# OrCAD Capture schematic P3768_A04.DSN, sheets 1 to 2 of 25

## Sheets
1 0024_FAN, DEBUG and EEPROM: size Custom
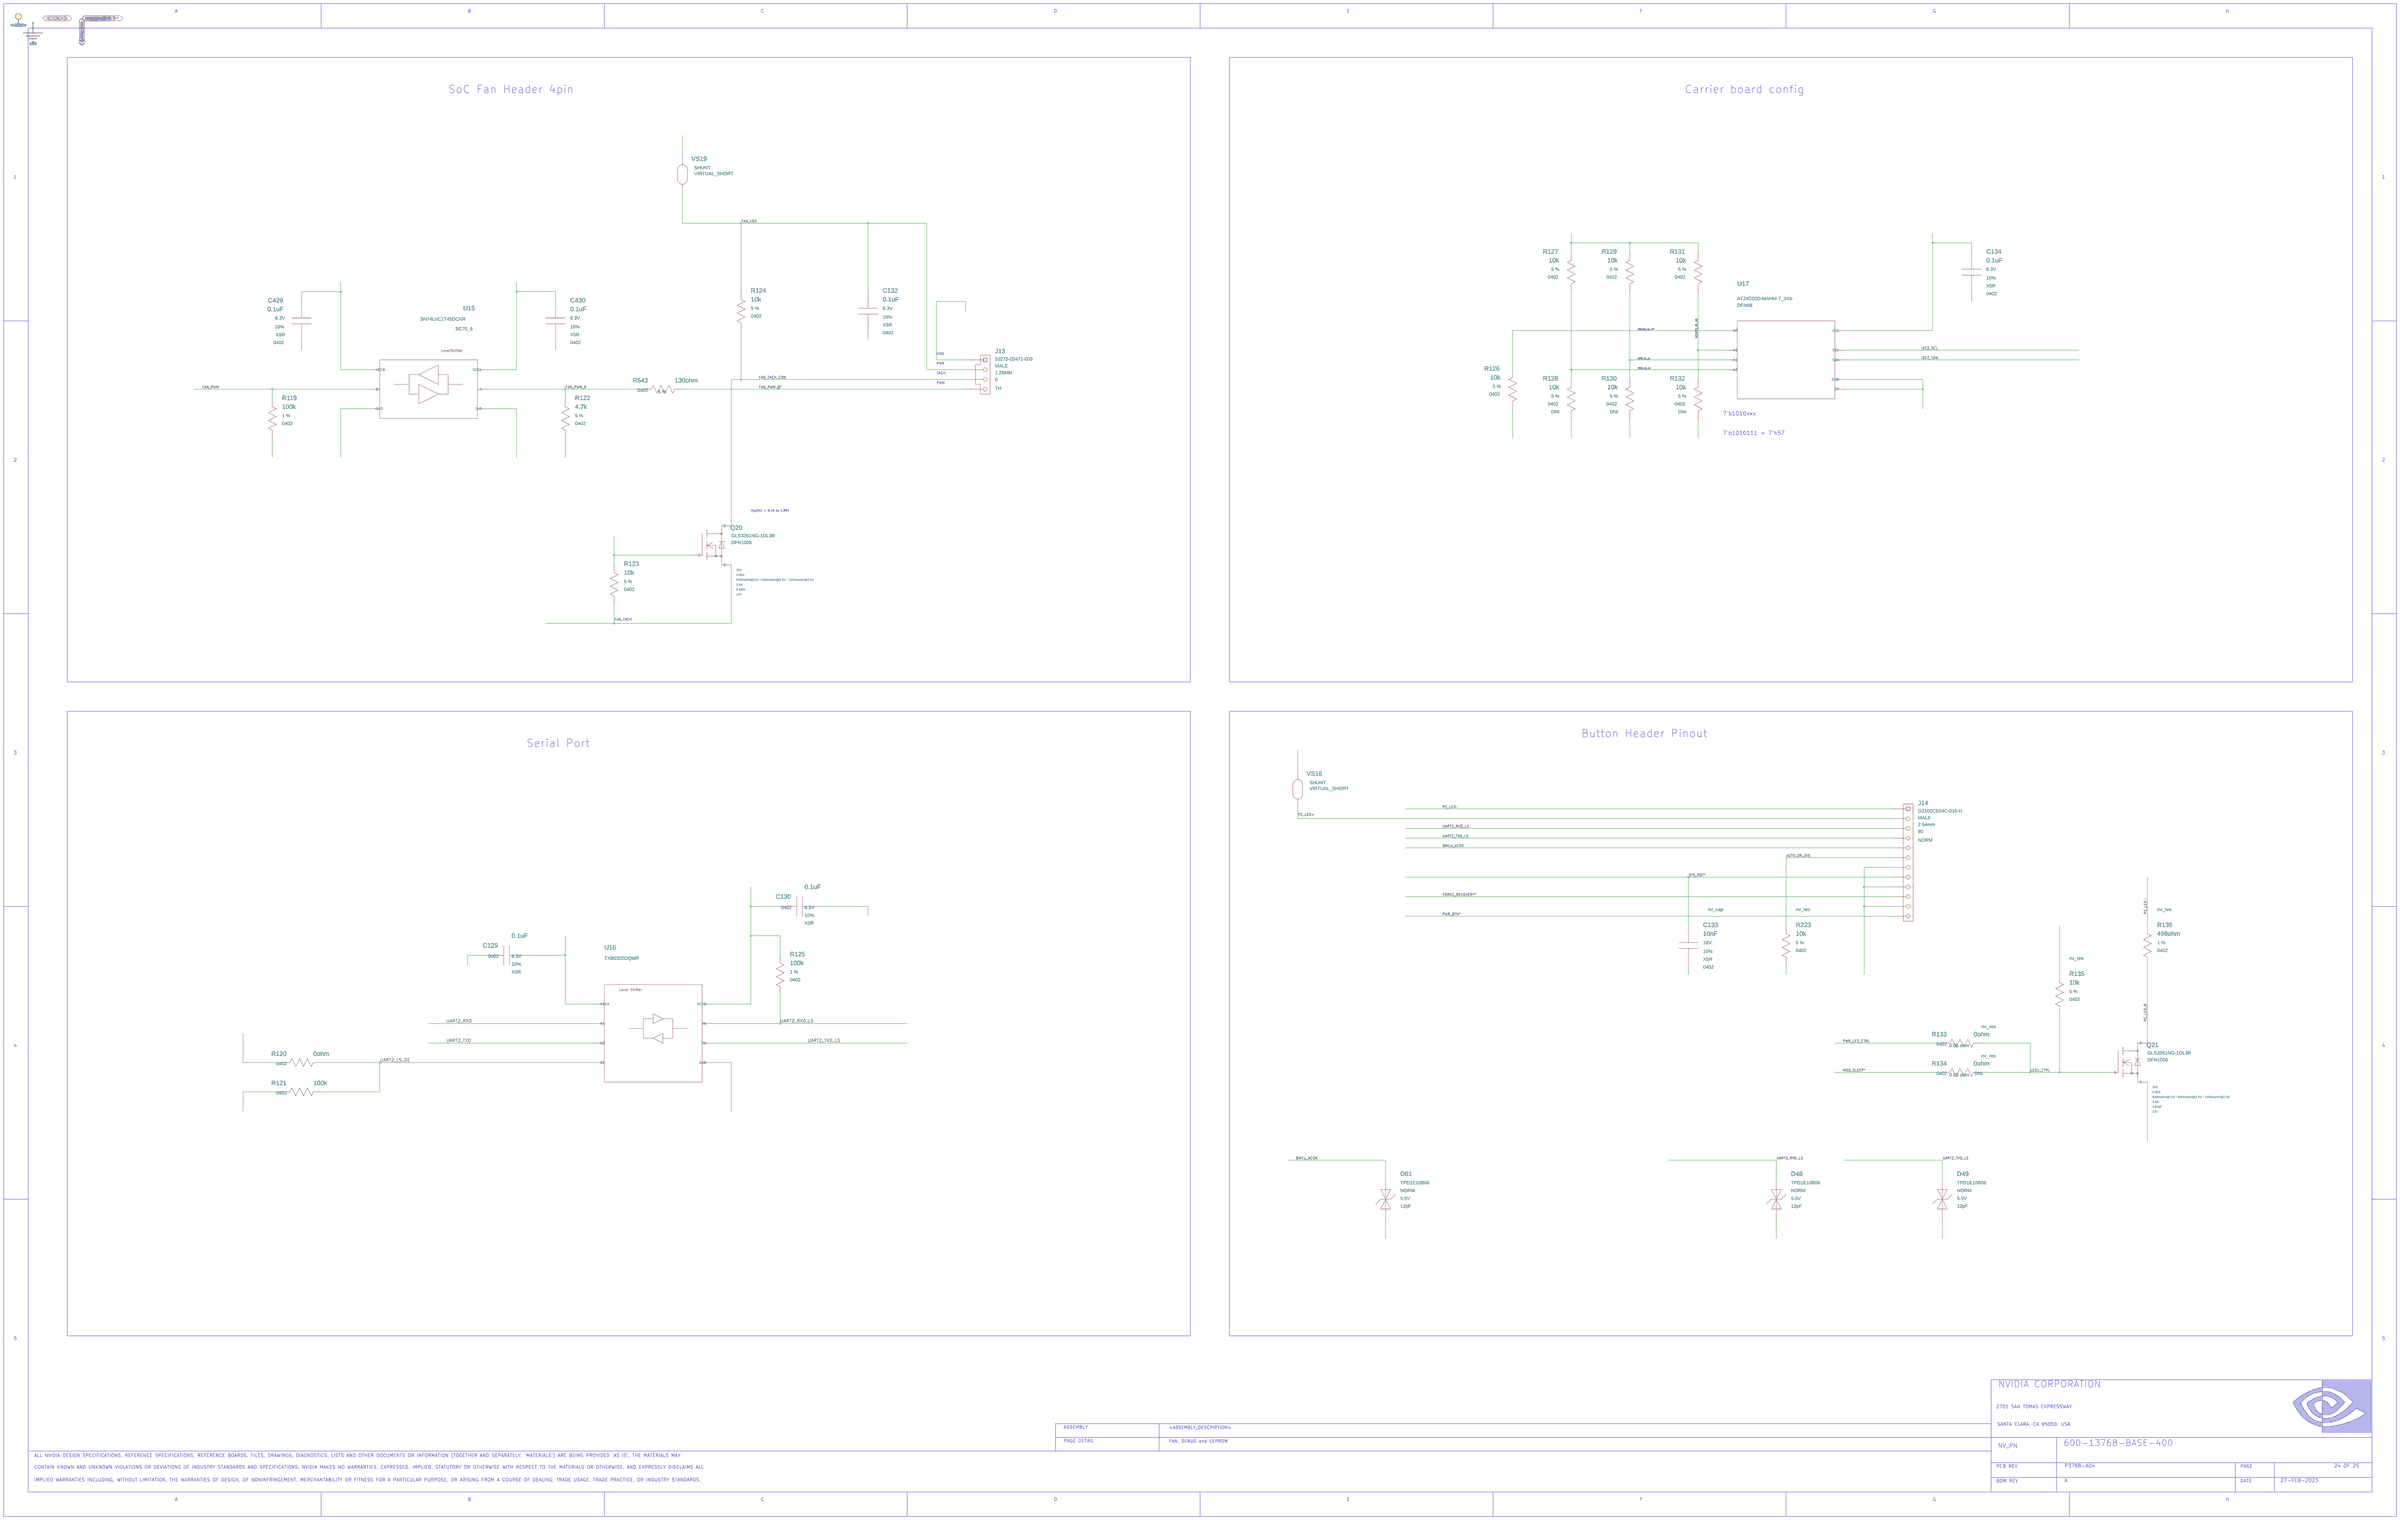
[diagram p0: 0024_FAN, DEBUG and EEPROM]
2 0023_40PIN GPIO Expansion HDR: size Custom
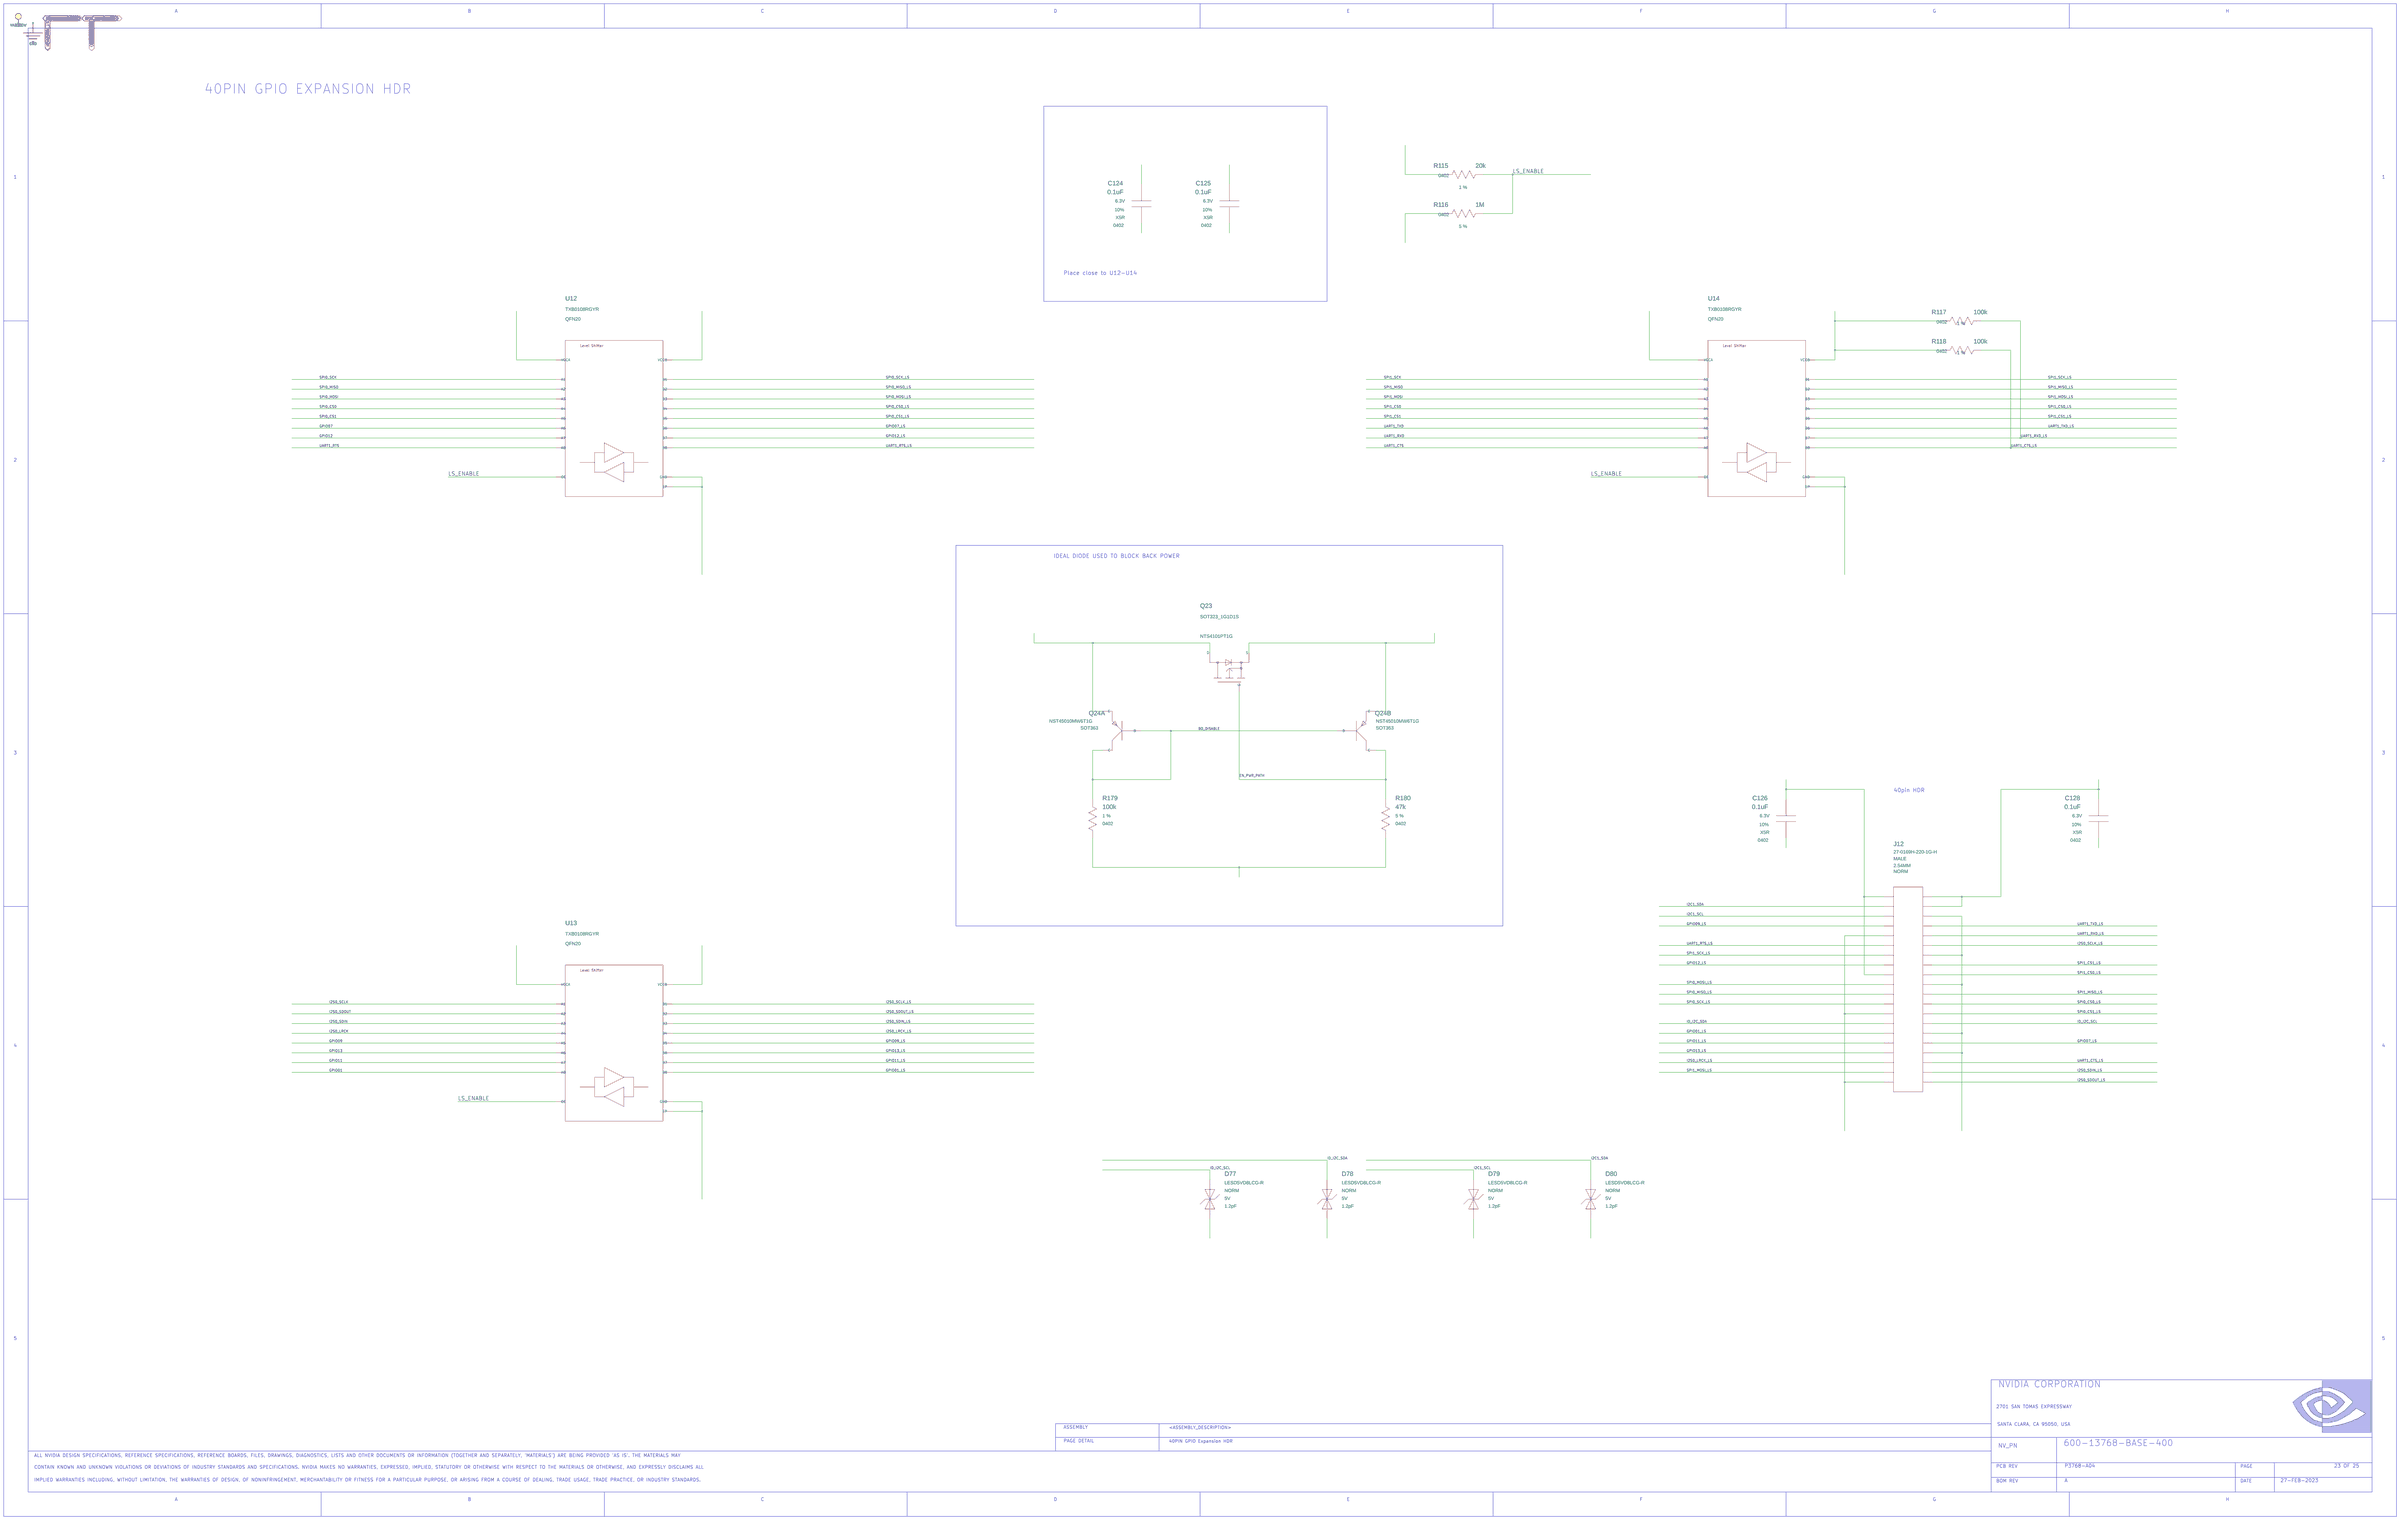
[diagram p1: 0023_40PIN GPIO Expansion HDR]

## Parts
sheet 0023_40PIN GPIO Expansion HDR
C124  0.1uF  [0402]
C125  0.1uF  [0402]
C126  0.1uF  [0402]
C128  0.1uF  [0402]
D77  D_ESD  [DIODE_SMD_010X006_B]
D78  D_ESD  [DIODE_SMD_010X006_B]
D79  D_ESD  [DIODE_SMD_010X006_B]
D80  D_ESD  [DIODE_SMD_010X006_B]
J12  HDR_2X20  [CON_HDR_002X020_TH_ST_M_P025_B]
Q23  Q_FET_P_ENH  [SOT323]
Q24  Q_PNP  [SC70_6]  (sections A,B)
R115  20k  [0402]
R116  1M  [0402]
R117  100k  [0402]
R118  100k  [0402]
R179  100k  [0402]
R180  47k  [0402]
U12  U_LEVSHFT_TXB0108  [QFN020R_P050_0045X0035_T031X021_VIAS]
U13  U_LEVSHFT_TXB0108  [QFN020R_P050_0045X0035_T031X021_VIAS]
U14  U_LEVSHFT_TXB0108  [QFN020R_P050_0045X0035_T031X021_VIAS]
sheet 0024_FAN, DEBUG and EEPROM
C129  0.1uF  [0402]
C130  0.1uF  [0402]
C132  0.1uF  [0402]
C133  10nF  [0402]
C134  0.1uF  [0402]
C429  0.1uF  [0402]
C430  0.1uF  [0402]
D48  D_ESD  [DIODE_SMD_010X060]
D49  D_ESD  [DIODE_SMD_010X060]
D81  D_ESD  [DIODE_SMD_010X060]
J13  CON_B2W_1X4  [CON_MISC_004_TH_ST_M_P013_WTB]
J14  HDR_1X12  [CON_HDR_001X012_TH_RA_M_P025]
Q20  Q_FET_N_ENH  [DFET_003_SMD_010X006_B]
Q21  Q_FET_N_ENH  [DFET_003_SMD_010X006_B]
R119  100k  [0402]
R120  0ohm  [0402]
R121  100k  [0402]
R122  4.7k  [0402]
R123  10k  [0402]
R124  10k  [0402]
R125  100k  [0402]
R126  10k  [0402]
R127  10k  [0402]
R128  10k  [0402]
R129  10k  [0402]
R130  10k  [0402]
R131  10k  [0402]
R132  10k  [0402]
R133  0ohm  [0402]
R134  0ohm  [0402]
R135  10k  [0402]
R136  499ohm  [0402]
R223  10k  [0402]
R543  130ohm  [0402]
U15  U_LEVSHFT_3STATE  [SC70_6]
U16  U_LEVSHFT_TXB0302  [DFN08_P040_018X012]
U17  U_MEM_EE_I2C  [DFN08_P050_020X030_T014X014]
VS16  VIRTUAL_SHORT  [VIRTUAL_SHORT]
VS19  VIRTUAL_SHORT  [VIRTUAL_SHORT]

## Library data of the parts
C124 = C#1: ASSEMBLY: GPIO_HDR; CDS_LIB: discrete; CDS_PART_NAME: C_0402-0.1UF,X5R,10%,6.3V,039-0007-000; CDS_PHYS_PART_NAME: C_0402-0.1UF,X5R,10%,6.3V,039-0007-000-0.1UF,039-0007-000; CDS_SEC: 1; CHIPS_PART_NAME: C; DEVICE_TYPENAME: C_0402-01UFX5R1063V039-0007-000-01UF039-0007-000; DRAWING: @P3768_A04_LIB.P3768_A04(SCH_1):PAGE23; ESL: N/A; ESR: N/A; MAT: X5R; MAX_VOLTAGE: 6.3V; NV_PN: 039-0007-000; PATH: I68; PHYS_PAGE: 23; PSPICETEMPLATE: X^@REFDES  %1    %2   @NV_PN; ROT: 2; SEC: 1; SIGNAL_MODEL: nv_cap; TOL: 10%; VER: 1; XY: (-6300,6600)
C125 = C#1: ASSEMBLY: GPIO_HDR; CDS_LIB: discrete; CDS_PART_NAME: C_0402-0.1UF,X5R,10%,6.3V,039-0007-000; CDS_PHYS_PART_NAME: C_0402-0.1UF,X5R,10%,6.3V,039-0007-000-0.1UF,039-0007-000; CDS_SEC: 1; CHIPS_PART_NAME: C; DEVICE_TYPENAME: C_0402-01UFX5R1063V039-0007-000-01UF039-0007-000; DRAWING: @P3768_A04_LIB.P3768_A04(SCH_1):PAGE23; ESL: N/A; ESR: N/A; MAT: X5R; MAX_VOLTAGE: 6.3V; NV_PN: 039-0007-000; PATH: I57; PHYS_PAGE: 23; PSPICETEMPLATE: X^@REFDES  %1    %2   @NV_PN; ROT: 2; SEC: 1; SIGNAL_MODEL: nv_cap; TOL: 10%; VER: 1; XY: (-5850,6600)
C126 = C#1: ASSEMBLY: GPIO_HDR; CDS_LIB: discrete; CDS_PART_NAME: C_0402-0.1UF,X5R,10%,6.3V,039-0007-000; CDS_PHYS_PART_NAME: C_0402-0.1UF,X5R,10%,6.3V,039-0007-000-0.1UF,039-0007-000; CDS_SEC: 1; CHIPS_PART_NAME: C; DEVICE_TYPENAME: C_0402-01UFX5R1063V039-0007-000-01UF039-0007-000; DRAWING: @P3768_A04_LIB.P3768_A04(SCH_1):PAGE23; ESL: N/A; ESR: N/A; MAT: X5R; MAX_VOLTAGE: 6.3V; NV_PN: 039-0007-000; PATH: I40; PHYS_PAGE: 23; PSPICETEMPLATE: X^@REFDES  %1    %2   @NV_PN; ROT: 2; SEC: 1; SIGNAL_MODEL: nv_cap; TOL: 10%; VER: 1; XY: (-3000,3450)
C128 = C#1: ASSEMBLY: GPIO_HDR; CDS_LIB: discrete; CDS_PART_NAME: C_0402-0.1UF,X5R,10%,6.3V,039-0007-000; CDS_PHYS_PART_NAME: C_0402-0.1UF,X5R,10%,6.3V,039-0007-000-0.1UF,039-0007-000; CDS_SEC: 1; CHIPS_PART_NAME: C; DEVICE_TYPENAME: C_0402-01UFX5R1063V039-0007-000-01UF039-0007-000; DRAWING: @P3768_A04_LIB.P3768_A04(SCH_1):PAGE23; ESL: N/A; ESR: N/A; MAT: X5R; MAX_VOLTAGE: 6.3V; NV_PN: 039-0007-000; PATH: I31; PHYS_PAGE: 23; PSPICETEMPLATE: X^@REFDES  %1    %2   @NV_PN; ROT: 2; SEC: 1; SIGNAL_MODEL: nv_cap; TOL: 10%; VER: 1; XY: (-1400,3450)
D77 = D_ESD: ASSEMBLY: GPIO_HDR; BREAKDOWN_VOLTAGE_MIN_TYP: 5.5V; CAPACITANCE_MAX_TYP: 1.2pF; CDS_LIB: discrete; CDS_PART_NAME: D_ESD_NORM-LESD5VD8LCG-R,1 LINE,BI-DIRECTIONAL,5V,0.05UA,5.5V,10V@2A,1.2PF,090-0172-000; CDS_PHYS_PART_NAME: D_ESD_NORM-LESD5VD8LCG-R,1 LINE,BI-DIRECTIONAL,5V,0.05UA,5.5V,10V@2A,1.2PF,090-0172-000-090-0172-000; CDS_SEC: 1; CLAMPING_VOLTAGE: 10V@2A; CONFIGURATION: 1 Line; DEVICE_TYPENAME: D_ESD_NORM-LESD5VD8LCG-R1LINEBI-DIRECTIONAL5V005UA55V10V2A12PF090-0172-000-090-0172-000; DRAWING: @P3768_A04_LIB.P3768_A04(SCH_1):PAGE23; MAX_REVERSE_LEAKAGE_CURRENT: 0.05uA; MAX_REVERSE_VOLTAGE: 5V; NV_NAME: LESD5VD8LCG-R; NV_PN: 090-0172-000; PACK_TYPE: NORM; PATH: I84; PHYS_PAGE: 23; POLARITY: Bi-Directional; ROT: 0; SEC: 1; VER: 2; XY: (-5950,1500)
D78 = D_ESD: ASSEMBLY: GPIO_HDR; BREAKDOWN_VOLTAGE_MIN_TYP: 5.5V; CAPACITANCE_MAX_TYP: 1.2pF; CDS_LIB: discrete; CDS_PART_NAME: D_ESD_NORM-LESD5VD8LCG-R,1 LINE,BI-DIRECTIONAL,5V,0.05UA,5.5V,10V@2A,1.2PF,090-0172-000; CDS_PHYS_PART_NAME: D_ESD_NORM-LESD5VD8LCG-R,1 LINE,BI-DIRECTIONAL,5V,0.05UA,5.5V,10V@2A,1.2PF,090-0172-000-090-0172-000; CDS_SEC: 1; CLAMPING_VOLTAGE: 10V@2A; CONFIGURATION: 1 Line; DEVICE_TYPENAME: D_ESD_NORM-LESD5VD8LCG-R1LINEBI-DIRECTIONAL5V005UA55V10V2A12PF090-0172-000-090-0172-000; DRAWING: @P3768_A04_LIB.P3768_A04(SCH_1):PAGE23; MAX_REVERSE_LEAKAGE_CURRENT: 0.05uA; MAX_REVERSE_VOLTAGE: 5V; NV_NAME: LESD5VD8LCG-R; NV_PN: 090-0172-000; PACK_TYPE: NORM; PATH: I82; PHYS_PAGE: 23; POLARITY: Bi-Directional; ROT: 0; SEC: 1; VER: 2; XY: (-5350,1500)
D79 = D_ESD: ASSEMBLY: GPIO_HDR; BREAKDOWN_VOLTAGE_MIN_TYP: 5.5V; CAPACITANCE_MAX_TYP: 1.2pF; CDS_LIB: discrete; CDS_PART_NAME: D_ESD_NORM-LESD5VD8LCG-R,1 LINE,BI-DIRECTIONAL,5V,0.05UA,5.5V,10V@2A,1.2PF,090-0172-000; CDS_PHYS_PART_NAME: D_ESD_NORM-LESD5VD8LCG-R,1 LINE,BI-DIRECTIONAL,5V,0.05UA,5.5V,10V@2A,1.2PF,090-0172-000-090-0172-000; CDS_SEC: 1; CLAMPING_VOLTAGE: 10V@2A; CONFIGURATION: 1 Line; DEVICE_TYPENAME: D_ESD_NORM-LESD5VD8LCG-R1LINEBI-DIRECTIONAL5V005UA55V10V2A12PF090-0172-000-090-0172-000; DRAWING: @P3768_A04_LIB.P3768_A04(SCH_1):PAGE23; MAX_REVERSE_LEAKAGE_CURRENT: 0.05uA; MAX_REVERSE_VOLTAGE: 5V; NV_NAME: LESD5VD8LCG-R; NV_PN: 090-0172-000; PACK_TYPE: NORM; PATH: I79; PHYS_PAGE: 23; POLARITY: Bi-Directional; ROT: 0; SEC: 1; VER: 2; XY: (-4600,1500)
D80 = D_ESD: ASSEMBLY: GPIO_HDR; BREAKDOWN_VOLTAGE_MIN_TYP: 5.5V; CAPACITANCE_MAX_TYP: 1.2pF; CDS_LIB: discrete; CDS_PART_NAME: D_ESD_NORM-LESD5VD8LCG-R,1 LINE,BI-DIRECTIONAL,5V,0.05UA,5.5V,10V@2A,1.2PF,090-0172-000; CDS_PHYS_PART_NAME: D_ESD_NORM-LESD5VD8LCG-R,1 LINE,BI-DIRECTIONAL,5V,0.05UA,5.5V,10V@2A,1.2PF,090-0172-000-090-0172-000; CDS_SEC: 1; CLAMPING_VOLTAGE: 10V@2A; CONFIGURATION: 1 Line; DEVICE_TYPENAME: D_ESD_NORM-LESD5VD8LCG-R1LINEBI-DIRECTIONAL5V005UA55V10V2A12PF090-0172-000-090-0172-000; DRAWING: @P3768_A04_LIB.P3768_A04(SCH_1):PAGE23; MAX_REVERSE_LEAKAGE_CURRENT: 0.05uA; MAX_REVERSE_VOLTAGE: 5V; NV_NAME: LESD5VD8LCG-R; NV_PN: 090-0172-000; PACK_TYPE: NORM; PATH: I78; PHYS_PAGE: 23; POLARITY: Bi-Directional; ROT: 0; SEC: 1; VER: 2; XY: (-4000,1500)
J12 = HDR_2X20: ANGLE: 0; ASSEMBLY: GPIO_HDR; CDS_LIB: electro_mechanic; CDS_PART_NAME: HDR_2X20_NORM-27-0169H-220-1G-H,MALE,2.54MM,0,YES,NO,NO,1000 V,3 A,074-0221-000; CDS_PHYS_PART_NAME: HDR_2X20_NORM-27-0169H-220-1G-H,MALE,2.54MM,0,YES,NO,NO,1000 V,3 A,074-0221-000-074-0221-000; CDS_SEC: 1; DEVICE_TYPENAME: HDR_2X20_NORM-27-0169H-220-1G-HMALE254MM0YESNONO1000V3A074-0221-000-074-0221-000; DRAWING: @P3768_A04_LIB.P3768_A04(SCH_1):PAGE23; GENDER: MALE; LATCHING: NO; MAX_CURRENT: 3 A; MAX_VOLTAGE: 1000 V; NV_NAME: 27-0169H-220-1G-H; NV_PN: 074-0221-000; PACK_TYPE: NORM; PATH: I1; PHYS_PAGE: 23; PITCH: 2.54MM; REFLOW: YES; ROT: 0; SEC: 1; SHROUDED: NO; VER: 1; XY: (-2350,2550)
Q23 = Q_FET_P_ENH#2: ASSEMBLY: GPIO_HDR; CDS_LIB: discrete; CDS_PART_NAME: Q_FET_P_ENH_SOT323_1G1D1S-NTS4101PT1G,-20V,0MOHM@10V / 120MOHM@4.5V / 160MOHM@2.5V,-1.37A,-4A,8V,0.329W,[ ]@10V / 9NC@4.5V / [ ]@2.5V,300-0859-000; CDS_PHYS_PART_NAME: Q_FET_P_ENH_SOT323_1G1D1S-NTS4101PT1G,-20V,0MOHM@10V / 120MOHM@4.5V / 160MOHM@2.5V,-1.37A,-4A,8V,0.329W,[ ]@10V / 9NC@4.5V / [B; CDS_SEC: 1; CONTINUOUS_CURRENT: -1.37A; DEVICE_TYPENAME: Q_FET_P_ENH_SOT323_1G1D1S-NTS4101PT1G-20V0MOHM10V120MOHM45V160MOHM25V-137A-4A8V0329W10V9NC45VB; DRAWING: @P3768_A04_LIB.P3768_A04(SCH_1):PAGE23; MAX_CURRENT: -4A; MAX_VOLTAGE: -20V; MAX_WATTAGE: 0.329W; NV_NAME: NTS4101PT1G; NV_PN: 300-0859-000; PACK_TYPE: SOT323_1G1D1S; PATH: I203; PHYS_PAGE: 23; Q_G: [ ]@10V / 9nC@4.5V / [ ]@2.5V; ROT: 4; R_DS_ON: 0mohm@10V / 120mohm@4.5V / 160mohm@2.5V; SEC: 1; SEC_TYPE: SOT323_1G1D1S; VER: 10; V_BE_GS: 8V; XY: (-5850,4200)
Q24 = Q_PNP: ASSEMBLY: GPIO_HDR; CDS_LIB: discrete; CDS_PART_NAME: Q_PNP_SOT363-NST45010MW6T1G,-45V,-50V,-0.1A,-0.1A,-5V,0.1MW,300-0906-000; CDS_PHYS_PART_NAME: Q_PNP_SOT363-NST45010MW6T1G,-45V,-50V,-0.1A,-0.1A,-5V,0.1MW,300-0906-000-300-0906-000; CDS_SEC: 2; CONTINUOUS_CURRENT: -0.1A; DEVICE_TYPENAME: Q_PNP_SOT363-NST45010MW6T1G-45V-50V-01A-01A-5V01MW300-0906-000-300-0906-000; DRAWING: @P3768_A04_LIB.P3768_A04(SCH_1):PAGE23; MAX_CURRENT: -0.1A; MAX_VOLTAGE: -45V; MAX_WATTAGE: 0.1mW; NV_NAME: NST45010MW6T1G; NV_PN: 300-0906-000; PACK_TYPE: SOT363; PATH: I209; PHYS_PAGE: 23; ROT: 0; SEC: 2; VER: 2; V_BE_GS: -5V; V_CE_SAT: -50V; XY: (-5200,3900)
R115 = R#1: ASSEMBLY: GPIO_HDR; CDS_LIB: discrete; CDS_PART_NAME: R_0402-20K,1 %,62.5MW,195-0150-000; CDS_PHYS_PART_NAME: R_0402-20K,1 %,62.5MW,195-0150-000-195-0150-000,20K; CDS_SEC: 1; CHIPS_PART_NAME: R; DEVICE_TYPENAME: R_0402-20K1625MW195-0150-000-195-0150-00020K; DRAWING: @P3768_A04_LIB.P3768_A04(SCH_1):PAGE23; MAX_WATTAGE: 62.5mW; NV_PN: 195-0150-000; PATH: I98; PHYS_PAGE: 23; PSPICETEMPLATE: X^@REFDES  %1    %2   @NV_PN; ROT: 0; SEC: 1; SIGNAL_MODEL: nv_res; TOL: 1 %; VER: 1; XY: (-4650,6750)
R116 = R#1: ASSEMBLY: GPIO_HDR; CDS_LIB: discrete; CDS_PART_NAME: R_0402-1M,5 %,62.5MW,195-0488-000; CDS_PHYS_PART_NAME: R_0402-1M,5 %,62.5MW,195-0488-000-195-0488-000,1M; CDS_SEC: 1; CHIPS_PART_NAME: R; DEVICE_TYPENAME: R_0402-1M5625MW195-0488-000-195-0488-0001M; DRAWING: @P3768_A04_LIB.P3768_A04(SCH_1):PAGE23; MAX_WATTAGE: 62.5mW; NV_PN: 195-0488-000; PATH: I100; PHYS_PAGE: 23; PSPICETEMPLATE: X^@REFDES  %1    %2   @NV_PN; ROT: 0; SEC: 1; SIGNAL_MODEL: nv_res; TOL: 5 %; VER: 1; XY: (-4650,6550)
R117 = R#1: ASSEMBLY: GPIO_HDR; CDS_LIB: discrete; CDS_PART_NAME: R_0402-100K,1 %,62.5MW,195-0005-000; CDS_PHYS_PART_NAME: R_0402-100K,1 %,62.5MW,195-0005-000-100K,195-0005-000; CDS_SEC: 1; CHIPS_PART_NAME: R; DEVICE_TYPENAME: R_0402-100K1625MW195-0005-000-100K195-0005-000; DRAWING: @P3768_A04_LIB.P3768_A04(SCH_1):PAGE23; MAX_WATTAGE: 62.5mW; NV_PN: 195-0005-000; PATH: I13; PHYS_PAGE: 23; PSPICETEMPLATE: X^@REFDES  %1    %2   @NV_PN; ROT: 0; SEC: 1; SIGNAL_MODEL: nv_res; TOL: 1 %; VER: 1; XY: (-2100,6000)
R118 = R#1: ASSEMBLY: GPIO_HDR; CDS_LIB: discrete; CDS_PART_NAME: R_0402-100K,1 %,62.5MW,195-0005-000; CDS_PHYS_PART_NAME: R_0402-100K,1 %,62.5MW,195-0005-000-100K,195-0005-000; CDS_SEC: 1; CHIPS_PART_NAME: R; DEVICE_TYPENAME: R_0402-100K1625MW195-0005-000-100K195-0005-000; DRAWING: @P3768_A04_LIB.P3768_A04(SCH_1):PAGE23; MAX_WATTAGE: 62.5mW; NV_PN: 195-0005-000; PATH: I14; PHYS_PAGE: 23; PSPICETEMPLATE: X^@REFDES  %1    %2   @NV_PN; ROT: 0; SEC: 1; SIGNAL_MODEL: nv_res; TOL: 1 %; VER: 1; XY: (-2100,5850)
R179 = R: ASSEMBLY: GPIO_HDR; CDS_LIB: discrete; CDS_PART_NAME: R_0402-100K,1 %,62.5MW,195-0005-000; CDS_PHYS_PART_NAME: R_0402-100K,1 %,62.5MW,195-0005-000-100K,195-0005-000; CDS_SEC: 1; DEVICE_TYPENAME: R_0402-100K1625MW195-0005-000-100K195-0005-000; DRAWING: @P3768_A04_LIB.P3768_A04(SCH_1):PAGE23; MAX_WATTAGE: 62.5mW; NV_PN: 195-0005-000; PATH: I211; PHYS_PAGE: 23; PSPICETEMPLATE: X^@REFDES  %1    %2   @NV_PN; ROT: 0; SEC: 1; SIGNAL_MODEL: nv_res; TOL: 1 %; VER: 2; XY: (-6550,3450)
R180 = R: ASSEMBLY: GPIO_HDR; CDS_LIB: discrete; CDS_PART_NAME: R_0402-47K,5 %,62.5MW,195-0599-000; CDS_PHYS_PART_NAME: R_0402-47K,5 %,62.5MW,195-0599-000-195-0599-000,47K; CDS_SEC: 1; DEVICE_TYPENAME: R_0402-47K5625MW195-0599-000-195-0599-00047K; DRAWING: @P3768_A04_LIB.P3768_A04(SCH_1):PAGE23; MAX_WATTAGE: 62.5mW; NV_PN: 195-0599-000; PATH: I212; PHYS_PAGE: 23; PSPICETEMPLATE: X^@REFDES  %1    %2   @NV_PN; ROT: 0; SEC: 1; SIGNAL_MODEL: nv_res; TOL: 5 %; VER: 2; XY: (-5050,3450)
U12 = U_LEVSHFT_TXB0108: ASSEMBLY: GPIO_HDR; CDS_LIB: digital; CDS_PART_NAME: U_LEVSHFT_TXB0108_QFN20-TXB0108RGYR,LEVEL SHIFTER,115-1921-000; CDS_PHYS_PART_NAME: U_LEVSHFT_TXB0108_QFN20-TXB0108RGYR,LEVEL SHIFTER,115-1921-000-115-1921-000; CDS_SEC: 1; DEVICE_TYPENAME: U_LEVSHFT_TXB0108_QFN20-TXB0108RGYRLEVELSHIFTER115-1921-000-115-1921-000; DRAWING: @P3768_A04_LIB.P3768_A04(SCH_1):PAGE23; FUNCTION: Level Shifter; NV_NAME: TXB0108RGYR; NV_PN: 115-1921-000; PACK_TYPE: QFN20; PATH: I97; PHYS_PAGE: 23; ROT: 0; SEC: 1; VER: 1; XY: (-9000,5550)
U13 = U_LEVSHFT_TXB0108: ASSEMBLY: GPIO_HDR; CDS_LIB: digital; CDS_PART_NAME: U_LEVSHFT_TXB0108_QFN20-TXB0108RGYR,LEVEL SHIFTER,115-1921-000; CDS_PHYS_PART_NAME: U_LEVSHFT_TXB0108_QFN20-TXB0108RGYR,LEVEL SHIFTER,115-1921-000-115-1921-000; CDS_SEC: 1; DEVICE_TYPENAME: U_LEVSHFT_TXB0108_QFN20-TXB0108RGYRLEVELSHIFTER115-1921-000-115-1921-000; DRAWING: @P3768_A04_LIB.P3768_A04(SCH_1):PAGE23; FUNCTION: Level Shifter; NV_NAME: TXB0108RGYR; NV_PN: 115-1921-000; PACK_TYPE: QFN20; PATH: I115; PHYS_PAGE: 23; ROT: 0; SEC: 1; VER: 1; XY: (-9000,2350)
U14 = U_LEVSHFT_TXB0108: ASSEMBLY: GPIO_HDR; CDS_LIB: digital; CDS_PART_NAME: U_LEVSHFT_TXB0108_QFN20-TXB0108RGYR,LEVEL SHIFTER,115-1921-000; CDS_PHYS_PART_NAME: U_LEVSHFT_TXB0108_QFN20-TXB0108RGYR,LEVEL SHIFTER,115-1921-000-115-1921-000; CDS_SEC: 1; DEVICE_TYPENAME: U_LEVSHFT_TXB0108_QFN20-TXB0108RGYRLEVELSHIFTER115-1921-000-115-1921-000; DRAWING: @P3768_A04_LIB.P3768_A04(SCH_1):PAGE23; FUNCTION: Level Shifter; NV_NAME: TXB0108RGYR; NV_PN: 115-1921-000; PACK_TYPE: QFN20; PATH: I19; PHYS_PAGE: 23; ROT: 0; SEC: 1; VER: 1; XY: (-3150,5550)
C129 = C: ASSEMBLY: DEBUG; CDS_LIB: discrete; CDS_PART_NAME: C_0402-0.1UF,X5R,10%,6.3V,039-0007-000; CDS_PHYS_PART_NAME: C_0402-0.1UF,X5R,10%,6.3V,039-0007-000-0.1UF,039-0007-000; CDS_SEC: 1; DEVICE_TYPENAME: C_0402-01UFX5R1063V039-0007-000-01UF039-0007-000; DRAWING: @P3768_A04_LIB.P3768_A04(SCH_1):PAGE24; MAT: X5R; MAX_VOLTAGE: 6.3V; NV_PN: 039-0007-000; PATH: I77; PHYS_PAGE: 24; PSPICETEMPLATE: X^@REFDES  %1    %2   @NV_PN; ROT: 0; SEC: 1; SIGNAL_MODEL: nv_cap; TOL: 10%; VER: 2; XY: (-9550,2750)
C130 = C: ASSEMBLY: DEBUG; CDS_LIB: discrete; CDS_PART_NAME: C_0402-0.1UF,X5R,10%,6.3V,039-0007-000; CDS_PHYS_PART_NAME: C_0402-0.1UF,X5R,10%,6.3V,039-0007-000-0.1UF,039-0007-000; CDS_SEC: 1; DEVICE_TYPENAME: C_0402-01UFX5R1063V039-0007-000-01UF039-0007-000; DRAWING: @P3768_A04_LIB.P3768_A04(SCH_1):PAGE24; MAT: X5R; MAX_VOLTAGE: 6.3V; NV_PN: 039-0007-000; PATH: I57; PHYS_PAGE: 24; PSPICETEMPLATE: X^@REFDES  %1    %2   @NV_PN; ROT: 0; SEC: 1; SIGNAL_MODEL: nv_cap; TOL: 10%; VER: 2; XY: (-8050,3000)
C132 = C#1: ASSEMBLY: FAN; CDS_LIB: discrete; CDS_PART_NAME: C_0402-0.1UF,X5R,10%,6.3V,039-0007-000; CDS_PHYS_PART_NAME: C_0402-0.1UF,X5R,10%,6.3V,039-0007-000-0.1UF,039-0007-000; CDS_SEC: 1; CHIPS_PART_NAME: C; DEVICE_TYPENAME: C_0402-01UFX5R1063V039-0007-000-01UF039-0007-000; DRAWING: @P3768_A04_LIB.P3768_A04(SCH_1):PAGE24; MAT: X5R; MAX_VOLTAGE: 6.3V; NV_PN: 039-0007-000; PATH: I2; PHYS_PAGE: 24; PSPICETEMPLATE: X^@REFDES  %1    %2   @NV_PN; ROT: 0; SEC: 1; SIGNAL_MODEL: nv_cap; TOL: 10%; VER: 1; XY: (-7700,6050)
C133 = C#1: ASSEMBLY: AUTOMATION; CDS_LIB: discrete; CDS_PART_NAME: C_0402-10NF,X5R,10%,16V,039-0024-000; CDS_PHYS_PART_NAME: C_0402-10NF,X5R,10%,16V,039-0024-000-039-0024-000,10NF; CDS_SEC: 1; CHIPS_PART_NAME: C; DEVICE_TYPENAME: C_0402-10NFX5R1016V039-0024-000-039-0024-00010NF; DRAWING: @P3768_A04_LIB.P3768_A04(SCH_1):PAGE24; MAT: X5R; MAX_VOLTAGE: 16V; NV_PN: 039-0024-000; PATH: I31; PHYS_PAGE: 24; PSPICETEMPLATE: X^@REFDES  %1    %2   @NV_PN; ROT: 0; SEC: 1; SIGNAL_MODEL: nv_cap; TOL: 10%; VER: 1; XY: (-3500,2800)
C134 = C#1: ASSEMBLY: L4T_EEPROM; CDS_LIB: discrete; CDS_PART_NAME: C_0402-0.1UF,X5R,10%,6.3V,039-0007-000; CDS_PHYS_PART_NAME: C_0402-0.1UF,X5R,10%,6.3V,039-0007-000-0.1UF,039-0007-000; CDS_SEC: 1; CHIPS_PART_NAME: C; DEVICE_TYPENAME: C_0402-01UFX5R1063V039-0007-000-01UF039-0007-000; DRAWING: @P3768_A04_LIB.P3768_A04(SCH_1):PAGE24; MAT: X5R; MAX_VOLTAGE: 6.3V; NV_PN: 039-0007-000; PATH: I11; PHYS_PAGE: 24; PSPICETEMPLATE: X^@REFDES  %1    %2   @NV_PN; ROT: 0; SEC: 1; SIGNAL_MODEL: nv_cap; TOL: 10%; VER: 1; XY: (-2050,6250)
C429 = C#1: ASSEMBLY: FAN; CDS_LIB: discrete; CDS_PART_NAME: C_0402-0.1UF,X5R,10%,6.3V,039-0007-000; CDS_PHYS_PART_NAME: C_0402-0.1UF,X5R,10%,6.3V,039-0007-000-0.1UF,039-0007-000; CDS_SEC: 1; CHIPS_PART_NAME: C; DEVICE_TYPENAME: C_0402-01UFX5R1063V039-0007-000-01UF039-0007-000; DRAWING: @P3768_A04_LIB.P3768_A04(SCH_1):PAGE24; MAT: X5R; MAX_VOLTAGE: 6.3V; NV_PN: 039-0007-000; PATH: I103; PHYS_PAGE: 24; PSPICETEMPLATE: X^@REFDES  %1    %2   @NV_PN; ROT: 2; SEC: 1; SIGNAL_MODEL: nv_cap; TOL: 10%; VER: 1; XY: (-10600,6000)
C430 = C#1: ASSEMBLY: FAN; CDS_LIB: discrete; CDS_PART_NAME: C_0402-0.1UF,X5R,10%,6.3V,039-0007-000; CDS_PHYS_PART_NAME: C_0402-0.1UF,X5R,10%,6.3V,039-0007-000-0.1UF,039-0007-000; CDS_SEC: 1; CHIPS_PART_NAME: C; DEVICE_TYPENAME: C_0402-01UFX5R1063V039-0007-000-01UF039-0007-000; DRAWING: @P3768_A04_LIB.P3768_A04(SCH_1):PAGE24; MAT: X5R; MAX_VOLTAGE: 6.3V; NV_PN: 039-0007-000; PATH: I102; PHYS_PAGE: 24; PSPICETEMPLATE: X^@REFDES  %1    %2   @NV_PN; ROT: 0; SEC: 1; SIGNAL_MODEL: nv_cap; TOL: 10%; VER: 1; XY: (-9300,6000)
D48 = D_ESD: ASSEMBLY: AUTOMATION; BREAKDOWN_VOLTAGE_MIN_TYP: 6V; CAPACITANCE_MAX_TYP: 12pF; CDS_LIB: discrete; CDS_PART_NAME: D_ESD_NORM-TPD1E10B06,1 LINE,BI-DIRECTIONAL,5.5V,0.1UA,6V,10V@1A,12PF,090-0243-000; CDS_PHYS_PART_NAME: D_ESD_NORM-TPD1E10B06,1 LINE,BI-DIRECTIONAL,5.5V,0.1UA,6V,10V@1A,12PF,090-0243-000-090-0243-000; CDS_SEC: 1; CLAMPING_VOLTAGE: 10V@1A; CONFIGURATION: 1 Line; DEVICE_TYPENAME: D_ESD_NORM-TPD1E10B061LINEBI-DIRECTIONAL55V01UA6V10V1A12PF090-0243-000-090-0243-000; DRAWING: @P3768_A04_LIB.P3768_A04(SCH_1):PAGE24; MAX_REVERSE_LEAKAGE_CURRENT: 0.1uA; MAX_REVERSE_VOLTAGE: 5.5V; NV_NAME: TPD1E10B06; NV_PN: 090-0243-000; PACK_TYPE: NORM; PATH: I35; PHYS_PAGE: 24; POLARITY: Bi-Directional; ROT: 0; SEC: 1; VER: 2; XY: (-3050,1500)
D49 = D_ESD: ASSEMBLY: AUTOMATION; BREAKDOWN_VOLTAGE_MIN_TYP: 6V; CAPACITANCE_MAX_TYP: 12pF; CDS_LIB: discrete; CDS_PART_NAME: D_ESD_NORM-TPD1E10B06,1 LINE,BI-DIRECTIONAL,5.5V,0.1UA,6V,10V@1A,12PF,090-0243-000; CDS_PHYS_PART_NAME: D_ESD_NORM-TPD1E10B06,1 LINE,BI-DIRECTIONAL,5.5V,0.1UA,6V,10V@1A,12PF,090-0243-000-090-0243-000; CDS_SEC: 1; CLAMPING_VOLTAGE: 10V@1A; CONFIGURATION: 1 Line; DEVICE_TYPENAME: D_ESD_NORM-TPD1E10B061LINEBI-DIRECTIONAL55V01UA6V10V1A12PF090-0243-000-090-0243-000; DRAWING: @P3768_A04_LIB.P3768_A04(SCH_1):PAGE24; MAX_REVERSE_LEAKAGE_CURRENT: 0.1uA; MAX_REVERSE_VOLTAGE: 5.5V; NV_NAME: TPD1E10B06; NV_PN: 090-0243-000; PACK_TYPE: NORM; PATH: I33; PHYS_PAGE: 24; POLARITY: Bi-Directional; ROT: 0; SEC: 1; VER: 2; XY: (-2200,1500)
D81 = D_ESD: ASSEMBLY: AUTOMATION; BREAKDOWN_VOLTAGE_MIN_TYP: 6V; CAPACITANCE_MAX_TYP: 12pF; CDS_LIB: discrete; CDS_PART_NAME: D_ESD_NORM-TPD1E10B06,1 LINE,BI-DIRECTIONAL,5.5V,0.1UA,6V,10V@1A,12PF,090-0243-000; CDS_PHYS_PART_NAME: D_ESD_NORM-TPD1E10B06,1 LINE,BI-DIRECTIONAL,5.5V,0.1UA,6V,10V@1A,12PF,090-0243-000-090-0243-000; CDS_SEC: 1; CLAMPING_VOLTAGE: 10V@1A; CONFIGURATION: 1 Line; DEVICE_TYPENAME: D_ESD_NORM-TPD1E10B061LINEBI-DIRECTIONAL55V01UA6V10V1A12PF090-0243-000-090-0243-000; DRAWING: @P3768_A04_LIB.P3768_A04(SCH_1):PAGE24; MAX_REVERSE_LEAKAGE_CURRENT: 0.1uA; MAX_REVERSE_VOLTAGE: 5.5V; NV_NAME: TPD1E10B06; NV_PN: 090-0243-000; PACK_TYPE: NORM; PATH: I54; PHYS_PAGE: 24; POLARITY: Bi-Directional; ROT: 0; SEC: 1; VER: 2; XY: (-5050,1500)
J13 = CON_B2W_1X4: ANGLE: 0; ASSEMBLY: FAN; CDS_LIB: electro_mechanic; CDS_PART_NAME: CON_B2W_1X4_TH-50275-00471-003,MALE,1.25MM,0,YES,YES,NO,NO,N/A,NA,NA,064-0267-000; CDS_PHYS_PART_NAME: CON_B2W_1X4_TH-50275-00471-003,MALE,1.25MM,0,YES,YES,NO,NO,N/A,NA,NA,064-0267-000-064-0267-000; CDS_SEC: 1; DEVICE_TYPENAME: CON_B2W_1X4_TH-50275-00471-003MALE125MM0YESYESNONONANANA064-0267-000-064-0267-000; DRAWING: @P3768_A04_LIB.P3768_A04(SCH_1):PAGE24; EMI_GROUND_TAB: NO; GENDER: MALE; LATCHING: NO; MAX_CURRENT: NA; MAX_VOLTAGE: NA; NV_NAME: 50275-00471-003; NV_PN: 064-0267-000; PACK_TYPE: TH; PATH: I91; PHYS_PAGE: 24; PITCH: 1.25MM; REFLOW: YES; ROT: 0; SEC: 1; SEC_TYPE: TH; SHIELDED: N/A; SHROUDED: YES; VER: 1; XY: (-7100,5800)
J14 = HDR_1X12: ANGLE: 90; ASSEMBLY: AUTOMATION; CDS_LIB: electro_mechanic; CDS_PART_NAME: HDR_1X12_NORM-G2100CE04C-016-H,MALE,2.54MM,90,YES,NO,NO,125 V,3 A,074-0239-000; CDS_PHYS_PART_NAME: HDR_1X12_NORM-G2100CE04C-016-H,MALE,2.54MM,90,YES,NO,NO,125 V,3 A,074-0239-000-074-0239-000; CDS_SEC: 1; DEVICE_TYPENAME: HDR_1X12_NORM-G2100CE04C-016-HMALE254MM90YESNONO125V3A074-0239-000-074-0239-000; DRAWING: @P3768_A04_LIB.P3768_A04(SCH_1):PAGE24; GENDER: MALE; LATCHING: NO; MAX_CURRENT: 3 A; MAX_VOLTAGE: 125 V; NV_NAME: G2100CE04C-016-H; NV_PN: 074-0239-000; PACK_TYPE: NORM; PATH: I25; PHYS_PAGE: 24; PITCH: 2.54mm; REFLOW: YES; ROT: 0; SEC: 1; SHROUDED: NO; VER: 1; XY: (-2400,3250)
Q20 = Q_FET_N_ENH#1: ASSEMBLY: FAN; CDS_LIB: discrete; CDS_PART_NAME: Q_FET_N_ENH_DFN1006-GLS3261NG-1DL3R,30V,600MOHM@10V / 650MOHM@4.5V / 1200MOHM@2.5V,0.95A,3.8A,12V,0.83W,0NC@10V / 0NC@4.5V / 0NC@2.5V,300-1253-000; CDS_PHYS_PART_NAME: Q_FET_N_ENH_DFN1006-GLS3261NG-1DL3R,30V,600MOHM@10V / 650MOHM@4.5V / 1200MOHM@2.5V,0.95A,3.8A,12V,0.83W,0NC@10V / 0NC@4.5V / 0B; CDS_SEC: 1; CONTINUOUS_CURRENT: 0.95A; CaptureCellPackProp: Q_FET_N_ENH##1; DEVICE_TYPENAME: Q_FET_N_ENH_DFN1006-GLS3261NG-1DL3R30V600MOHM10V650MOHM45V1200MOHM25V095A38A12V083W0NC10V0NC45V0B; DRAWING: @P3768_A04_LIB.P3768_A04(SCH_1):PAGE24; MAX_CURRENT: 3.8A; MAX_VOLTAGE: 30V; MAX_WATTAGE: 0.83W; NV_NAME: GLS3261NG-1DL3R; NV_PN: 300-1253-000; PACK_TYPE: DFN1006; PATH: I3; PHYS_PAGE: 24; Q_G: 0nC@10V / 0nC@4.5V / 0nC@2.5V; ROT: 0; R_DS_ON: 600mohm@10V / 650mohm@4.5V / 1200mohm@2.5V; SEC: 1; VER: 2; V_BE_GS: 12V; XY: (-8500,4850)
Q21 = Q_FET_N_ENH#1: ASSEMBLY: AUTOMATION; CDS_LIB: discrete; CDS_PART_NAME: Q_FET_N_ENH_DFN1006-GLS3261NG-1DL3R,30V,600MOHM@10V / 650MOHM@4.5V / 1200MOHM@2.5V,0.95A,3.8A,12V,0.83W,0NC@10V / 0NC@4.5V / 0NC@2.5V,300-1253-000; CDS_PHYS_PART_NAME: Q_FET_N_ENH_DFN1006-GLS3261NG-1DL3R,30V,600MOHM@10V / 650MOHM@4.5V / 1200MOHM@2.5V,0.95A,3.8A,12V,0.83W,0NC@10V / 0NC@4.5V / 0B; CDS_SEC: 1; CONTINUOUS_CURRENT: 0.95A; CaptureCellPackProp: Q_FET_N_ENH##1; DEVICE_TYPENAME: Q_FET_N_ENH_DFN1006-GLS3261NG-1DL3R30V600MOHM10V650MOHM45V1200MOHM25V095A38A12V083W0NC10V0NC45V0B; DRAWING: @P3768_A04_LIB.P3768_A04(SCH_1):PAGE24; MAX_CURRENT: 3.8A; MAX_VOLTAGE: 30V; MAX_WATTAGE: 0.83W; NV_NAME: GLS3261NG-1DL3R; NV_PN: 300-1253-000; PACK_TYPE: DFN1006; PATH: I21; PHYS_PAGE: 24; Q_G: 0nC@10V / 0nC@4.5V / 0nC@2.5V; ROT: 0; R_DS_ON: 600mohm@10V / 650mohm@4.5V / 1200mohm@2.5V; SEC: 1; VER: 2; V_BE_GS: 12V; XY: (-1250,2200)
R119 = R: ASSEMBLY: FAN; CDS_LIB: discrete; CDS_PART_NAME: R_0402-100K,1 %,62.5MW,195-0005-000; CDS_PHYS_PART_NAME: R_0402-100K,1 %,62.5MW,195-0005-000-100K,195-0005-000; CDS_SEC: 1; DEVICE_TYPENAME: R_0402-100K1625MW195-0005-000-100K195-0005-000; DRAWING: @P3768_A04_LIB.P3768_A04(SCH_1):PAGE24; MAX_WATTAGE: 62.5mW; NV_PN: 195-0005-000; PATH: I71; PHYS_PAGE: 24; PSPICETEMPLATE: X^@REFDES  %1    %2   @NV_PN; ROT: 0; SEC: 1; SIGNAL_MODEL: nv_res; TOL: 1 %; VER: 2; XY: (-10750,5500)
R120 = R#1: ASSEMBLY: DEBUG; CDS_LIB: discrete; CDS_PART_NAME: R_0402-0OHM,0.05 OHM,62.5MW,195-2655-000; CDS_PHYS_PART_NAME: R_0402-0OHM,0.05 OHM,62.5MW,195-2655-000-0OHM,195-2655-000; CDS_SEC: 1; CHIPS_PART_NAME: R; DEVICE_TYPENAME: R_0402-0OHM005OHM625MW195-2655-000-0OHM195-2655-000; DRAWING: @P3768_A04_LIB.P3768_A04(SCH_1):PAGE24; MAX_WATTAGE: 62.5mW; NV_PN: 195-2655-000; PATH: I82; PHYS_PAGE: 24; PSPICETEMPLATE: X^@REFDES  %1    %2   @NV_PN; ROT: 0; SEC: 1; SIGNAL_MODEL: nv_res; TOL: 0.05 ohm; VER: 1; XY: (-10600,2200)
R121 = R#1: ASSEMBLY: DEBUG; CDS_LIB: discrete; CDS_PART_NAME: R_0402-100K,1 %,62.5MW,195-0005-000; CDS_PHYS_PART_NAME: R_0402-100K,1 %,62.5MW,195-0005-000-100K,195-0005-000; CDS_SEC: 1; CHIPS_PART_NAME: R; DEVICE_TYPENAME: R_0402-100K1625MW195-0005-000-100K195-0005-000; DRAWING: @P3768_A04_LIB.P3768_A04(SCH_1):PAGE24; MAX_WATTAGE: 62.5mW; NV_PN: 195-0005-000; PATH: I84; PHYS_PAGE: 24; PSPICETEMPLATE: X^@REFDES  %1    %2   @NV_PN; ROT: 0; SEC: 1; SIGNAL_MODEL: nv_res; TOL: 1 %; VER: 1; XY: (-10600,2050)
R122 = R: ASSEMBLY: FAN; CDS_LIB: discrete; CDS_PART_NAME: R_0402-4.7K,5 %,62.5MW,195-0598-000; CDS_PHYS_PART_NAME: R_0402-4.7K,5 %,62.5MW,195-0598-000-195-0598-000,4.7K; CDS_SEC: 1; DEVICE_TYPENAME: R_0402-47K5625MW195-0598-000-195-0598-00047K; DRAWING: @P3768_A04_LIB.P3768_A04(SCH_1):PAGE24; MAX_WATTAGE: 62.5mW; NV_PN: 195-0598-000; PATH: I64; PHYS_PAGE: 24; PSPICETEMPLATE: X^@REFDES  %1    %2   @NV_PN; ROT: 0; SEC: 1; SIGNAL_MODEL: nv_res; TOL: 5 %; VER: 2; XY: (-9250,5500)
R123 = R: ASSEMBLY: FAN; CDS_LIB: discrete; CDS_PART_NAME: R_0402-10K,5 %,62.5MW,195-0486-000; CDS_PHYS_PART_NAME: R_0402-10K,5 %,62.5MW,195-0486-000-10K,195-0486-000; CDS_SEC: 1; DEVICE_TYPENAME: R_0402-10K5625MW195-0486-000-10K195-0486-000; DRAWING: @P3768_A04_LIB.P3768_A04(SCH_1):PAGE24; MAX_WATTAGE: 62.5mW; NV_PN: 195-0486-000; PATH: I62; PHYS_PAGE: 24; PSPICETEMPLATE: X^@REFDES  %1    %2   @NV_PN; ROT: 0; SEC: 1; SIGNAL_MODEL: nv_res; TOL: 5 %; VER: 2; XY: (-9000,4650)
R124 = R: ASSEMBLY: FAN; CDS_LIB: discrete; CDS_PART_NAME: R_0402-10K,5 %,62.5MW,195-0486-000; CDS_PHYS_PART_NAME: R_0402-10K,5 %,62.5MW,195-0486-000-10K,195-0486-000; CDS_SEC: 1; DEVICE_TYPENAME: R_0402-10K5625MW195-0486-000-10K195-0486-000; DRAWING: @P3768_A04_LIB.P3768_A04(SCH_1):PAGE24; MAX_WATTAGE: 62.5mW; NV_PN: 195-0486-000; PATH: I60; PHYS_PAGE: 24; PSPICETEMPLATE: X^@REFDES  %1    %2   @NV_PN; ROT: 0; SEC: 1; SIGNAL_MODEL: nv_res; TOL: 5 %; VER: 2; XY: (-8350,6050)
R125 = R: ASSEMBLY: DEBUG; CDS_LIB: discrete; CDS_PART_NAME: R_0402-100K,1 %,62.5MW,195-0005-000; CDS_PHYS_PART_NAME: R_0402-100K,1 %,62.5MW,195-0005-000-100K,195-0005-000; CDS_SEC: 1; DEVICE_TYPENAME: R_0402-100K1625MW195-0005-000-100K195-0005-000; DRAWING: @P3768_A04_LIB.P3768_A04(SCH_1):PAGE24; MAX_WATTAGE: 62.5mW; NV_PN: 195-0005-000; PATH: I58; PHYS_PAGE: 24; PSPICETEMPLATE: X^@REFDES  %1    %2   @NV_PN; ROT: 0; SEC: 1; SIGNAL_MODEL: nv_res; TOL: 1 %; VER: 2; XY: (-8150,2650)
R126 = R: ASSEMBLY: L4T_EEPROM; CDS_LIB: discrete; CDS_PART_NAME: R_0402-10K,5 %,62.5MW,195-0486-000; CDS_PHYS_PART_NAME: R_0402-10K,5 %,62.5MW,195-0486-000-10K,195-0486-000; CDS_SEC: 1; DEVICE_TYPENAME: R_0402-10K5625MW195-0486-000-10K195-0486-000; DRAWING: @P3768_A04_LIB.P3768_A04(SCH_1):PAGE24; MAX_WATTAGE: 62.5mW; NV_PN: 195-0486-000; PATH: I42; PHYS_PAGE: 24; PSPICETEMPLATE: X^@REFDES  %1    %2   @NV_PN; ROT: 2; SEC: 1; SIGNAL_MODEL: nv_res; TOL: 5 %; VER: 2; XY: (-4400,5650)
R127 = R: ASSEMBLY: L4T_EEPROM; CDS_LIB: discrete; CDS_PART_NAME: R_0402-10K,5 %,62.5MW,195-0486-000; CDS_PHYS_PART_NAME: R_0402-10K,5 %,62.5MW,195-0486-000-10K,195-0486-000; CDS_SEC: 1; DEVICE_TYPENAME: R_0402-10K5625MW195-0486-000-10K195-0486-000; DRAWING: @P3768_A04_LIB.P3768_A04(SCH_1):PAGE24; MAX_WATTAGE: 62.5mW; NV_PN: 195-0486-000; PATH: I39; PHYS_PAGE: 24; PSPICETEMPLATE: X^@REFDES  %1    %2   @NV_PN; ROT: 2; SEC: 1; SIGNAL_MODEL: nv_res; TOL: 5 %; VER: 2; XY: (-4100,6250)
R128 = R: ASSEMBLY: L4T_EEPROM; CDS_LIB: discrete; CDS_PART_NAME: R_0402-10K,5 %,62.5MW,195-0486-000; CDS_PHYS_PART_NAME: R_0402-10K,5 %,62.5MW,195-0486-000-10K,195-0486-000; CDS_SEC: 1; DEVICE_TYPENAME: R_0402-10K5625MW195-0486-000-10K195-0486-000; DRAWING: @P3768_A04_LIB.P3768_A04(SCH_1):PAGE24; MAX_WATTAGE: 62.5mW; NV_PN: 195-0486-000; PATH: I40; PHYS_PAGE: 24; PSPICETEMPLATE: X^@REFDES  %1    %2   @NV_PN; ROT: 2; SEC: 1; SIGNAL_MODEL: nv_res; SKU: DNI; TOL: 5 %; VER: 2; XY: (-4100,5600)
R129 = R: ASSEMBLY: L4T_EEPROM; CDS_LIB: discrete; CDS_PART_NAME: R_0402-10K,5 %,62.5MW,195-0486-000; CDS_PHYS_PART_NAME: R_0402-10K,5 %,62.5MW,195-0486-000-10K,195-0486-000; CDS_SEC: 1; DEVICE_TYPENAME: R_0402-10K5625MW195-0486-000-10K195-0486-000; DRAWING: @P3768_A04_LIB.P3768_A04(SCH_1):PAGE24; MAX_WATTAGE: 62.5mW; NV_PN: 195-0486-000; PATH: I17; PHYS_PAGE: 24; PSPICETEMPLATE: X^@REFDES  %1    %2   @NV_PN; ROT: 2; SEC: 1; SIGNAL_MODEL: nv_res; TOL: 5 %; VER: 2; XY: (-3800,6250)
R130 = R: ASSEMBLY: L4T_EEPROM; CDS_LIB: discrete; CDS_PART_NAME: R_0402-10K,5 %,62.5MW,195-0486-000; CDS_PHYS_PART_NAME: R_0402-10K,5 %,62.5MW,195-0486-000-10K,195-0486-000; CDS_SEC: 1; DEVICE_TYPENAME: R_0402-10K5625MW195-0486-000-10K195-0486-000; DRAWING: @P3768_A04_LIB.P3768_A04(SCH_1):PAGE24; MAX_WATTAGE: 62.5mW; NV_PN: 195-0486-000; PATH: I18; PHYS_PAGE: 24; PSPICETEMPLATE: X^@REFDES  %1    %2   @NV_PN; ROT: 2; SEC: 1; SIGNAL_MODEL: nv_res; SKU: DNI; TOL: 5 %; VER: 2; XY: (-3800,5600)
R131 = R: ASSEMBLY: L4T_EEPROM; CDS_LIB: discrete; CDS_PART_NAME: R_0402-10K,5 %,62.5MW,195-0486-000; CDS_PHYS_PART_NAME: R_0402-10K,5 %,62.5MW,195-0486-000-10K,195-0486-000; CDS_SEC: 1; DEVICE_TYPENAME: R_0402-10K5625MW195-0486-000-10K195-0486-000; DRAWING: @P3768_A04_LIB.P3768_A04(SCH_1):PAGE24; MAX_WATTAGE: 62.5mW; NV_PN: 195-0486-000; PATH: I13; PHYS_PAGE: 24; PSPICETEMPLATE: X^@REFDES  %1    %2   @NV_PN; ROT: 2; SEC: 1; SIGNAL_MODEL: nv_res; TOL: 5 %; VER: 2; XY: (-3450,6250)
R132 = R: ASSEMBLY: L4T_EEPROM; CDS_LIB: discrete; CDS_PART_NAME: R_0402-10K,5 %,62.5MW,195-0486-000; CDS_PHYS_PART_NAME: R_0402-10K,5 %,62.5MW,195-0486-000-10K,195-0486-000; CDS_SEC: 1; DEVICE_TYPENAME: R_0402-10K5625MW195-0486-000-10K195-0486-000; DRAWING: @P3768_A04_LIB.P3768_A04(SCH_1):PAGE24; MAX_WATTAGE: 62.5mW; NV_PN: 195-0486-000; PATH: I15; PHYS_PAGE: 24; PSPICETEMPLATE: X^@REFDES  %1    %2   @NV_PN; ROT: 2; SEC: 1; SIGNAL_MODEL: nv_res; SKU: DNI; TOL: 5 %; VER: 2; XY: (-3450,5600)
R133 = R#1: ASSEMBLY: AUTOMATION; CDS_LIB: discrete; CDS_PART_NAME: R_0402-0OHM,0.05 OHM,62.5MW,195-2655-000; CDS_PHYS_PART_NAME: R_0402-0OHM,0.05 OHM,62.5MW,195-2655-000-0OHM,195-2655-000; CDS_SEC: 1; CHIPS_PART_NAME: R; DEVICE_TYPENAME: R_0402-0OHM005OHM625MW195-2655-000-0OHM195-2655-000; DRAWING: @P3768_A04_LIB.P3768_A04(SCH_1):PAGE24; MAX_WATTAGE: 62.5mW; NV_PN: 195-2655-000; PATH: I26; PHYS_PAGE: 24; PSPICETEMPLATE: X^@REFDES  %1    %2   @NV_PN; ROT: 0; SEC: 1; SIGNAL_MODEL: nv_res; TOL: 0.05 ohm; VER: 1; XY: (-2100,2300)
R134 = R#1: ASSEMBLY: AUTOMATION; CDS_LIB: discrete; CDS_PART_NAME: R_0402-0OHM,0.05 OHM,62.5MW,195-2655-000; CDS_PHYS_PART_NAME: R_0402-0OHM,0.05 OHM,62.5MW,195-2655-000-0OHM,195-2655-000; CDS_SEC: 1; CHIPS_PART_NAME: R; DEVICE_TYPENAME: R_0402-0OHM005OHM625MW195-2655-000-0OHM195-2655-000; DRAWING: @P3768_A04_LIB.P3768_A04(SCH_1):PAGE24; MAX_WATTAGE: 62.5mW; NV_PN: 195-2655-000; PATH: I27; PHYS_PAGE: 24; PSPICETEMPLATE: X^@REFDES  %1    %2   @NV_PN; ROT: 0; SEC: 1; SIGNAL_MODEL: nv_res; SKU: DNI; TOL: 0.05 ohm; VER: 1; XY: (-2100,2150)
R135 = R: ASSEMBLY: AUTOMATION; CDS_LIB: discrete; CDS_PART_NAME: R_0402-10K,5 %,62.5MW,195-0486-000; CDS_PHYS_PART_NAME: R_0402-10K,5 %,62.5MW,195-0486-000-10K,195-0486-000; CDS_SEC: 1; DEVICE_TYPENAME: R_0402-10K5625MW195-0486-000-10K195-0486-000; DRAWING: @P3768_A04_LIB.P3768_A04(SCH_1):PAGE24; MAX_WATTAGE: 62.5mW; NV_PN: 195-0486-000; PATH: I23; PHYS_PAGE: 24; PSPICETEMPLATE: X^@REFDES  %1    %2   @NV_PN; ROT: 0; SEC: 1; SIGNAL_MODEL: nv_res; TOL: 5 %; VER: 2; XY: (-1600,2550)
R136 = R: ASSEMBLY: AUTOMATION; CDS_LIB: discrete; CDS_PART_NAME: R_0402-499OHM,1 %,62.5MW,195-0338-000; CDS_PHYS_PART_NAME: R_0402-499OHM,1 %,62.5MW,195-0338-000-195-0338-000,499OHM; CDS_SEC: 1; DEVICE_TYPENAME: R_0402-499OHM1625MW195-0338-000-195-0338-000499OHM; DRAWING: @P3768_A04_LIB.P3768_A04(SCH_1):PAGE24; MAX_WATTAGE: 62.5mW; NV_PN: 195-0338-000; PATH: I20; PHYS_PAGE: 24; PSPICETEMPLATE: X^@REFDES  %1    %2   @NV_PN; ROT: 0; SEC: 1; SIGNAL_MODEL: nv_res; TOL: 1 %; VER: 2; XY: (-1150,2800)
R223 = R: ASSEMBLY: AUTOMATION; CDS_LIB: discrete; CDS_PART_NAME: R_0402-10K,5 %,62.5MW,195-0486-000; CDS_PHYS_PART_NAME: R_0402-10K,5 %,62.5MW,195-0486-000-10K,195-0486-000; CDS_SEC: 1; DEVICE_TYPENAME: R_0402-10K5625MW195-0486-000-10K195-0486-000; DRAWING: @P3768_A04_LIB.P3768_A04(SCH_1):PAGE24; MAX_WATTAGE: 62.5mW; NV_PN: 195-0486-000; PATH: I97; PHYS_PAGE: 24; PSPICETEMPLATE: X^@REFDES  %1    %2   @NV_PN; ROT: 0; SEC: 1; SIGNAL_MODEL: nv_res; TOL: 5 %; VER: 2; XY: (-3000,2800)
R543 = R#1: ASSEMBLY: FAN; CDS_LIB: discrete; CDS_PART_NAME: R_0402-130OHM,5 %,62.5MW,195-0506-000; CDS_PHYS_PART_NAME: R_0402-130OHM,5 %,62.5MW,195-0506-000-130OHM,195-0506-000; CDS_SEC: 1; CHIPS_PART_NAME: R; DEVICE_TYPENAME: R_0402-130OHM5625MW195-0506-000-130OHM195-0506-000; DRAWING: @P3768_A04_LIB.P3768_A04(SCH_1):PAGE24; MAX_WATTAGE: 62.5mW; NV_PN: 195-0506-000; PATH: I99; PHYS_PAGE: 24; ROT: 0; SEC: 1; SIGNAL_MODEL: nv_res; TOL: 5 %; VER: 1; XY: (-8750,5650)
U15 = U_LEVSHFT_3STATE#1: ASSEMBLY: FAN; CDS_LIB: logic; CDS_PART_NAME: U_LEVSHFT_3STATE_SC70_6-SN74LVC1T45DCKR,LEVEL SHIFTER,115-2544-000; CDS_PHYS_PART_NAME: U_LEVSHFT_3STATE_SC70_6-SN74LVC1T45DCKR,LEVEL SHIFTER,115-2544-000-115-2544-000; CDS_SEC: 1; DEVICE_TYPENAME: U_LEVSHFT_3STATE_SC70_6-SN74LVC1T45DCKRLEVELSHIFTER115-2544-000-115-2544-000; DRAWING: @P3768_A04_LIB.P3768_A04(SCH_1):PAGE24; FUNCTION: Level Shifter; NV_NAME: SN74LVC1T45DCKR; NV_PN: 115-2544-000; PATH: I96; PHYS_PAGE: 24; ROT: 2; SEC: 1; VER: 1; XY: (-9950,5650)
U16 = U_LEVSHFT_TXB0302: ASSEMBLY: DEBUG; CDS_LIB: logic; CDS_PART_NAME: U_LEVSHFT_TXB0302_DFN8-TXB0302DQMR,LEVEL SHIFTER,115-2177-000; CDS_PHYS_PART_NAME: U_LEVSHFT_TXB0302_DFN8-TXB0302DQMR,LEVEL SHIFTER,115-2177-000-115-2177-000; CDS_SEC: 1; DEVICE_TYPENAME: U_LEVSHFT_TXB0302_DFN8-TXB0302DQMRLEVELSHIFTER115-2177-000-115-2177-000; DRAWING: @P3768_A04_LIB.P3768_A04(SCH_1):PAGE24; FUNCTION: Level Shifter; NV_NAME: TXB0302DQMR; NV_PN: 115-2177-000; PATH: I75; PHYS_PAGE: 24; ROT: 0; SEC: 1; VER: 1; XY: (-8800,2350)
U17 = U_MEM_EE_I2C: ASSEMBLY: L4T_EEPROM; CDS_LIB: memory; CDS_PART_NAME: U_MEM_EE_I2C_DFN08-1MHZ,1.7V..3.6V,AT24C02D-MAHM-T_1KB,174-0159-000; CDS_PHYS_PART_NAME: U_MEM_EE_I2C_DFN08-1MHZ,1.7V..3.6V,AT24C02D-MAHM-T_1KB,174-0159-000-174-0159-000; CDS_SEC: 1; DEVICE_TYPENAME: U_MEM_EE_I2C_DFN08-1MHZ17V36VAT24C02D-MAHM-T_1KB174-0159-000-174-0159-000; DRAWING: @P3768_A04_LIB.P3768_A04(SCH_1):PAGE24; NV_NAME: AT24C02D-MAHM-T_1Kb; NV_PN: 174-0159-000; PACK_TYPE: DFN08; PATH: I14; PHYS_PAGE: 24; POW: 1.7V..3.6V; ROT: 0; SEC: 1; SPEED_GRADE: 1MHz; VER: 2; XY: (-3000,5800)
VS16 = VIRTUAL_SHORT#1: ASSEMBLY: AUTOMATION; CDS_LIB: mechanic; CDS_PART_NAME: VIRTUAL_SHORT_SHUNT-VIRTUAL_SHORT; CDS_PHYS_PART_NAME: VIRTUAL_SHORT_SHUNT-VIRTUAL_SHORT; CDS_SEC: 1; DEVICE_TYPENAME: VIRTUAL_SHORT_SHUNT-VIRTUAL_SHORT; DRAWING: @P3768_A04_LIB.P3768_A04(SCH_1):PAGE24; PACK_TYPE: SHUNT; PATH: I51; PHYS_PAGE: 24; ROT: 0; SEC: 1; VER: 2; XY: (-5500,3600)
VS19 = VIRTUAL_SHORT#1: ASSEMBLY: AUTOMATION; CDS_LIB: mechanic; CDS_PART_NAME: VIRTUAL_SHORT_SHUNT-VIRTUAL_SHORT; CDS_PHYS_PART_NAME: VIRTUAL_SHORT_SHUNT-VIRTUAL_SHORT; CDS_SEC: 1; DEVICE_TYPENAME: VIRTUAL_SHORT_SHUNT-VIRTUAL_SHORT; DRAWING: @P3768_A04_LIB.P3768_A04(SCH_1):PAGE24; PACK_TYPE: SHUNT; PATH: I92; PHYS_PAGE: 24; ROT: 0; SEC: 1; VER: 2; XY: (-8650,6750)

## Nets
GND: C124.2 C125.2 C126.2 C128.2 C129.1 C130.2 C132.2 C133.2 C134.2 C429.2 C430.2 D48.2 D49.2 D77.2 D78.2 D79.2 D80.2 D81.2 J12.6 J12.9 J12.14 J12.20 J12.25 J12.30 J12.34 J12.39 J13.1 J14.7 J14.9 J14.11 Q21.2(S) R116.1 R119.2 R121.1 R122.2 R126.2 R128.2 R130.2 R132.2 R179.2 R180.2 R223.2 U12.11(GND) U12.21(EP) U13.11(GND) U13.21(EP) U14.11(GND) U14.21(EP) U15.2(GND) U15.5(DIR) U16.4(GND) U17.4(GND) U17.9(TP) ; also on sheet 3 4 5 6 7 8 9 10 11 12 13 14 15 16 17 18 19 21 25
VDD_1V8: C124.1 C129.2 C134.1 C429.1 Q20.1(G) R115.1 R120.1 R123.1 R127.1 R129.1 R131.1 R135.1 U12.2(VCCA) U13.2(VCCA) U14.2(VCCA) U15.6(VCCB) U16.1(VCCA) U17.8(VCC) ; also on sheet 3 5 8 12 14 19 21
VDD_3V3_SYS: C125.1 C126.1 C130.1 J12.1 J12.17 R117.1 R118.1 R125.1 U12.19(VCCB) U13.19(VCCB) U14.19(VCCB) U16.8(VCCB) ; also on sheet 3 4 5 6 7 8 11 12 14 15 19 20 21
VDD_5V_GPIO: C128.1 J12.2 J12.4 Q23.2(S) Q24.4(E)
VDD_5V_SYS: C430.1 Q23.3(D) Q24.1(E) U15.1(VCCA) VS16.1(A) VS19.1(A) ; also on sheet 8 9 10 11 12 13 14 15 16 17 21
AUTO_ON_DIS: J14.6 R223.1
BD_DISABLE: Q24.2(B) Q24.5(B) Q24.6(C) R179.1
BMCU_ACOK: D81.1 J14.5 ; also on sheet 13
BOARD_ID_A0: R131.2 R132.1 U17.1(A0)
BOARD_ID_WP: R126.1 U17.7(WP)
BRD_ID_A1: R129.2 R130.1 U17.2(A1)
BRD_ID_A2: R127.2 R128.1 U17.3(A2)
EN_PWR_PATH: Q23.1(G) Q24.3(C) R180.1
FAN_PWM: R119.1 U15.4(B) ; also on sheet 20
FAN_PWM_Q*: J13.4 R543.2
FAN_PWM_R: R122.1 R543.1 U15.3(A)
FAN_TACH: Q20.2(S) R123.2 ; also on sheet 20
FAN_TACH_CON: J13.3 Q20.3(D) R124.2
FAN_VDD: C132.1 J13.2 R124.1 VS19.2(B)
FORCE_RECOVERY*: J14.10 ; also on sheet 21
GPIO01: U13.9(A8) ; also on sheet 20
GPIO01_LS: J12.29 U13.12(B8)
GPIO07: U12.7(A6) ; also on sheet 20
GPIO07_LS: J12.32 U12.14(B6)
GPIO09: U13.6(A5) ; also on sheet 20
GPIO09_LS: J12.7 U13.15(B5)
GPIO11: U13.8(A7) ; also on sheet 20
GPIO11_LS: J12.31 U13.13(B7)
GPIO12: U12.8(A7) ; also on sheet 20
GPIO12_LS: J12.15 U12.13(B7)
GPIO13: U13.7(A6) ; also on sheet 20
GPIO13_LS: J12.33 U13.14(B6)
I2C1_SCL: D79.1 J12.5 ; also on sheet 21
I2C1_SDA: D80.1 J12.3 ; also on sheet 21
I2C2_SCL: U17.6(SCL) ; also on sheet 3 4 5 21
I2C2_SDA: U17.5(SDA) ; also on sheet 3 4 5 21
I2S0_LRCK: U13.5(A4) ; also on sheet 20
I2S0_LRCK_LS: J12.35 U13.16(B4)
I2S0_SCLK: U13.1(A1) ; also on sheet 20
I2S0_SCLK_LS: J12.12 U13.20(B1)
I2S0_SDIN: U13.4(A3) ; also on sheet 20
I2S0_SDIN_LS: J12.38 U13.17(B3)
I2S0_SDOUT: U13.3(A2) ; also on sheet 20
I2S0_SDOUT_LS: J12.40 U13.18(B2)
ID_I2C_SCL: D77.1 J12.28 ; also on sheet 12 21
ID_I2C_SDA: D78.1 J12.27 ; also on sheet 12 21
LED1_CTRL: Q21.1(G) R133.2 R134.2 R135.2
LS_ENABLE: R115.2 R116.2 U12.10(OE) U13.10(OE) U14.10(OE)
MOD_SLEEP*: R134.1 ; also on sheet 8 21
PC_LED+: J14.2 VS16.2(B)
PC_LED-: J14.1 R136.1
PC_LED_R: Q21.3(D) R136.2
PWR_BTN*: J14.12 ; also on sheet 13 21
PWR_LED_CTRL: R133.1 ; also on sheet 20 21
SPI0_CS0: U12.5(A4) ; also on sheet 20
SPI0_CS0_LS: J12.24 U12.16(B4)
SPI0_CS1: U12.6(A5) ; also on sheet 20
SPI0_CS1_LS: J12.26 U12.15(B5)
SPI0_MISO: U12.3(A2) ; also on sheet 20
SPI0_MISO_LS: J12.21 U12.18(B2)
SPI0_MOSI: U12.4(A3) ; also on sheet 20
SPI0_MOSI_LS: J12.19 U12.17(B3)
SPI0_SCK: U12.1(A1) ; also on sheet 20
SPI0_SCK_LS: J12.23 U12.20(B1)
SPI1_CS0: U14.5(A4) ; also on sheet 20
SPI1_CS0_LS: J12.18 U14.16(B4)
SPI1_CS1: U14.6(A5) ; also on sheet 20
SPI1_CS1_LS: J12.16 U14.15(B5)
SPI1_MISO: U14.3(A2) ; also on sheet 20
SPI1_MISO_LS: J12.22 U14.18(B2)
SPI1_MOSI: U14.4(A3) ; also on sheet 20
SPI1_MOSI_LS: J12.37 U14.17(B3)
SPI1_SCK: U14.1(A1) ; also on sheet 20
SPI1_SCK_LS: J12.13 U14.20(B1)
SYS_RST*: C133.1 J14.8 ; also on sheet 13 21
UART1_CTS: U14.9(A8) ; also on sheet 21
UART1_CTS_LS: J12.36 R118.2 U14.12(B8)
UART1_RTS: U12.9(A8) ; also on sheet 21
UART1_RTS_LS: J12.11 U12.12(B8)
UART1_RXD: U14.8(A7) ; also on sheet 21
UART1_RXD_LS: J12.10 R117.2 U14.13(B7)
UART1_TXD: U14.7(A6) ; also on sheet 21
UART1_TXD_LS: J12.8 U14.14(B6)
UART2_LS_OE: R120.2 R121.2 U16.5(OE)
UART2_RXD: U16.2(A1) ; also on sheet 21
UART2_RXD_LS: D48.1 J14.3 R125.2 U16.7(B1)
UART2_TXD: U16.3(A2) ; also on sheet 21
UART2_TXD_LS: D49.1 J14.4 U16.6(B2)

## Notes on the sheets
sheet 1
- A
- B
- C
- D
- E
- F
- G
- H
- SoC Fan Header 4pin
- Carrier board config
- 1
- 1
- GND
- PWR
- TACH
- PWM
- 7'b1010xxx
- 7'b1010111 = 7'h57
- 2
- 2
- Vgs(th) = 0.45 to 1.05V
- Button Header Pinout
- Serial Port
- 3
- 3
- 4
- 4
- 5
- 5
- NVIDIA CORPORATION
- 2701 SAN TOMAS EXPRESSWAY
- SANTA CLARA, CA 95050, USA
- ASSEMBLY
- <ASSEMBLY_DESCRIPTION>
- PAGE DETAIL
- FAN, DEBUG and EEPROM
- 600-13768-BASE-400
- NV_PN
- ALL NVIDIA DESIGN SPECIFICATIONS, REFERENCE SPECIFICATIONS, REFERENCE BOARDS, FILES, DRAWINGS, DIAGNOSTICS, LISTS AND OTHER DOCUMENTS OR INFORMATION (TOGETHER AND SEPARATELY, 'MATERIALS') ARE BEING PROVIDED 'AS IS'. THE MATERIALS MAY
- P3768-A04
- 24 OF 25
- CONTAIN KNOWN AND UNKNOWN VIOLATIONS OR DEVIATIONS OF INDUSTRY STANDARDS AND SPECIFICATIONS. NVIDIA MAKES NO WARRANTIES, EXPRESSED, IMPLIED, STATUTORY OR OTHERWISE WITH RESPECT TO THE MATERIALS OR OTHERWISE, AND EXPRESSLY DISCLAIMS ALL
- PCB REV
- PAGE
- IMPLIED WARRANTIES INCLUDING, WITHOUT LIMITATION, THE WARRANTIES OF DESIGN, OF NONINFRINGEMENT, MERCHANTABILITY OR FITNESS FOR A PARTICULAR PURPOSE, OR ARISING FROM A COURSE OF DEALING, TRADE USAGE, TRADE PRACTICE, OR INDUSTRY STANDARDS.
- BOM REV
- A
- DATE
- 27-FEB-2023
- A
- B
- C
- D
- E
- F
- G
- H
sheet 2
- A
- B
- C
- D
- E
- F
- G
- H
- 40PIN GPIO EXPANSION HDR
- 1
- 1
- Place close to U12-U14
- 2
- 2
- IDEAL DIODE USED TO BLOCK BACK POWER
- 3
- 3
- 40pin HDR
- 4
- 4
- 5
- 5
- NVIDIA CORPORATION
- 2701 SAN TOMAS EXPRESSWAY
- SANTA CLARA, CA 95050, USA
- ASSEMBLY
- <ASSEMBLY_DESCRIPTION>
- PAGE DETAIL
- 40PIN GPIO Expansion HDR
- 600-13768-BASE-400
- NV_PN
- ALL NVIDIA DESIGN SPECIFICATIONS, REFERENCE SPECIFICATIONS, REFERENCE BOARDS, FILES, DRAWINGS, DIAGNOSTICS, LISTS AND OTHER DOCUMENTS OR INFORMATION (TOGETHER AND SEPARATELY, 'MATERIALS') ARE BEING PROVIDED 'AS IS'. THE MATERIALS MAY
- P3768-A04
- 23 OF 25
- CONTAIN KNOWN AND UNKNOWN VIOLATIONS OR DEVIATIONS OF INDUSTRY STANDARDS AND SPECIFICATIONS. NVIDIA MAKES NO WARRANTIES, EXPRESSED, IMPLIED, STATUTORY OR OTHERWISE WITH RESPECT TO THE MATERIALS OR OTHERWISE, AND EXPRESSLY DISCLAIMS ALL
- PCB REV
- PAGE
- IMPLIED WARRANTIES INCLUDING, WITHOUT LIMITATION, THE WARRANTIES OF DESIGN, OF NONINFRINGEMENT, MERCHANTABILITY OR FITNESS FOR A PARTICULAR PURPOSE, OR ARISING FROM A COURSE OF DEALING, TRADE USAGE, TRADE PRACTICE, OR INDUSTRY STANDARDS.
- BOM REV
- A
- DATE
- 27-FEB-2023
- A
- B
- C
- D
- E
- F
- G
- H
